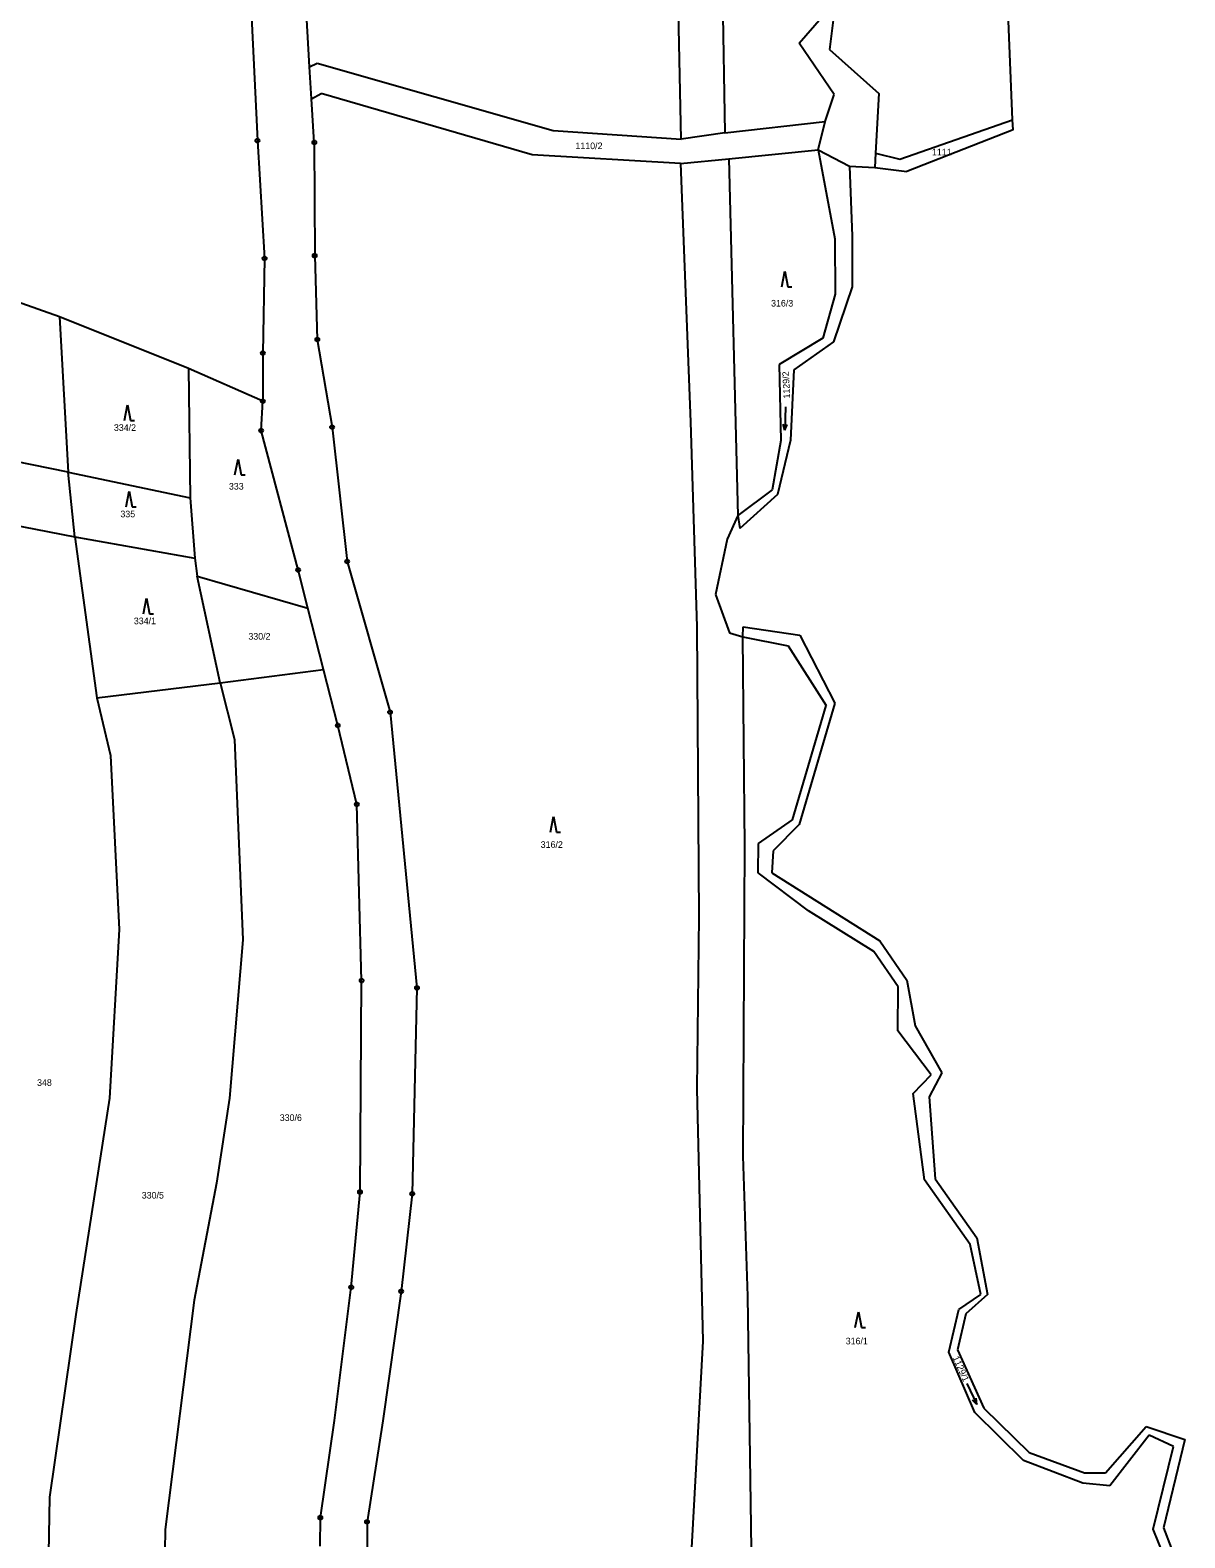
# Model space of a CAD drawing. Extents: x -794142 to -791199, y -1109267 to -1105626.
# Drawn here: x -792350.1 to -792053.1, y -1106886 to -1106498.2 of the extents above; entities that cross this region are included whole.
import ezdxf

# ---------------------------------------------------------------- set-up
doc = ezdxf.new("R2010")
doc.units = 0
for name, color, linetype in [('Vrstva 1', 7, 'Continuous'), ('Vrstva 14', 7, 'Continuous'), ('Vrstva 23', 7, 'Continuous'), ('Vrstva 28', 7, 'Continuous'), ('Vrstva 4', 7, 'Continuous')]:
    doc.layers.add(name, color=color, linetype=linetype)

msp = doc.modelspace()

# ---------------------------------------------------------------- linework, layer by layer
at = {"layer": 'Vrstva 1'}
for p, q in [((-792173.09, -1106426.36), (-792171.46, -1106524.59)), ((-792182.68, -1106526.22), (-792184.72, -1106430.3)), ((-792278.2, -1106507.65), (-792280.82, -1106464.66)), ((-792139.75, -1106464.02), (-792144.51, -1106503.18)), ((-792294.55, -1106465.43), (-792291.64, -1106526.62)), ((-792152.29, -1106501.53), (-792146.57, -1106494.99)), ((-792143.31, -1106514.79), (-792152.29, -1106501.53)), ((-792144.51, -1106503.18), (-792131.87, -1106514.52)), ((-792278.2, -1106507.65), (-792276.28, -1106506.69)), ((-792277.7, -1106515.86), (-792278.2, -1106507.65)), ((-792276.28, -1106506.69), (-792215.55, -1106524.04)), ((-792277.7, -1106515.86), (-792275.28, -1106514.53)), ((-792221.01, -1106530.25), (-792275.28, -1106514.53)), ((-792145.63, -1106521.72), (-792143.31, -1106514.79)), ((-792131.87, -1106514.52), (-792132.65, -1106529.9)), ((-792277.01, -1106527.1), (-792277.7, -1106515.86)), ((-792171.46, -1106524.59), (-792145.63, -1106521.72)), ((-792147.41, -1106529.04), (-792145.63, -1106521.72)), ((-792126.4, -1106531.43), (-792097.46, -1106521.3)), ((-792291.64, -1106526.62), (-792289.8, -1106556.92)), ((-792277.01, -1106527.1), (-792276.91, -1106556.22)), ((-792215.55, -1106524.04), (-792182.68, -1106526.22)), ((-792171.46, -1106524.59), (-792182.68, -1106526.22)), ((-792182.87, -1106532.49), (-792221.01, -1106530.25)), ((-792182.87, -1106532.49), (-792170.41, -1106531.28)), ((-792170.41, -1106531.28), (-792147.41, -1106529.04)), ((-792170.41, -1106531.28), (-792168.06, -1106623.03)), ((-792147.41, -1106529.04), (-792143.12, -1106551.85)), ((-792147.41, -1106529.04), (-792139.41, -1106533.21)), ((-792132.65, -1106529.9), (-792132.86, -1106533.57)), ((-792132.65, -1106529.9), (-792126.4, -1106531.43)), ((-792182.87, -1106532.49), (-792180.28, -1106598.96)), ((-792143.12, -1106551.85), (-792143.05, -1106566.11)), ((-792289.8, -1106556.92), (-792290.24, -1106581.27)), ((-792276.91, -1106556.22), (-792276.23, -1106577.77)), ((-792143.05, -1106566.11), (-792146.2, -1106577.44)), ((-792342.56, -1106571.94), (-792353.7, -1106568)), ((-792342.56, -1106571.94), (-792340.28, -1106611.92)), ((-792309.33, -1106585.21), (-792342.56, -1106571.94)), ((-792276.23, -1106577.77), (-792272.43, -1106600.33)), ((-792146.2, -1106577.44), (-792157.47, -1106584.23)), ((-792290.24, -1106581.27), (-792290.24, -1106593.67)), ((-792290.24, -1106593.67), (-792309.33, -1106585.21)), ((-792309.33, -1106585.21), (-792308.9, -1106618.5)), ((-792157.47, -1106584.23), (-792157, -1106603.73)), ((-792290.67, -1106601.2), (-792290.24, -1106593.67)), ((-792272.43, -1106600.33), (-792268.55, -1106634.86)), ((-792180.28, -1106598.96), (-792178.63, -1106651.72)), ((-792281.16, -1106637.04), (-792290.67, -1106601.2)), ((-792157, -1106603.73), (-792159.28, -1106616.41)), ((-792340.28, -1106611.92), (-792370.18, -1106605.87)), ((-792340.28, -1106611.92), (-792308.9, -1106618.5)), ((-792338.6, -1106628.51), (-792340.28, -1106611.92)), ((-792159.28, -1106616.41), (-792168.06, -1106623.03)), ((-792308.9, -1106618.5), (-792307.71, -1106633.98)), ((-792368.06, -1106622.79), (-792338.6, -1106628.51)), ((-792338.6, -1106628.51), (-792307.71, -1106633.98)), ((-792338.6, -1106628.51), (-792332.91, -1106669.92)), ((-792307.71, -1106633.98), (-792307.15, -1106638.68)), ((-792268.55, -1106634.86), (-792257.53, -1106673.63)), ((-792307.15, -1106638.68), (-792278.66, -1106646.86)), ((-792301.21, -1106666.11), (-792307.15, -1106638.68)), ((-792278.66, -1106646.86), (-792281.16, -1106637.04)), ((-792274.62, -1106662.68), (-792278.66, -1106646.86)), ((-792178.63, -1106651.72), (-792178.12, -1106726.25)), ((-792166.82, -1106654.29), (-792155.12, -1106656.54)), ((-792166.28, -1106708.06), (-792166.82, -1106654.29)), ((-792155.12, -1106656.54), (-792145.41, -1106671.91)), ((-792301.21, -1106666.11), (-792274.62, -1106662.68)), ((-792270.96, -1106677.04), (-792274.62, -1106662.68)), ((-792332.91, -1106669.92), (-792301.21, -1106666.11)), ((-792301.21, -1106666.11), (-792297.51, -1106680.66)), ((-792332.91, -1106669.92), (-792329.38, -1106684.74)), ((-792257.53, -1106673.63), (-792250.6, -1106744.55)), ((-792154.05, -1106701.34), (-792145.41, -1106671.91)), ((-792266.07, -1106697.34), (-792270.96, -1106677.04)), ((-792297.51, -1106680.66), (-792295.35, -1106732.22)), ((-792329.38, -1106684.74), (-792327.21, -1106729.54)), ((-792264.84, -1106742.65), (-792266.07, -1106697.34)), ((-792162.76, -1106707.37), (-792154.05, -1106701.34)), ((-792166.75, -1106787.84), (-792166.28, -1106708.06)), ((-792162.86, -1106714.98), (-792162.76, -1106707.37)), ((-792149.88, -1106724.72), (-792162.86, -1106714.98)), ((-792133.14, -1106735.14), (-792149.88, -1106724.72)), ((-792178.12, -1106726.25), (-792178.67, -1106770.51)), ((-792327.21, -1106729.54), (-792329.67, -1106772.89)), ((-792295.35, -1106732.22), (-792298.81, -1106772.87)), ((-792126.82, -1106744.25), (-792133.14, -1106735.14)), ((-792265.25, -1106797.04), (-792264.84, -1106742.65)), ((-792250.6, -1106744.55), (-792251.82, -1106797.49)), ((-792126.91, -1106755.57), (-792126.82, -1106744.25)), ((-792118.38, -1106766.88), (-792126.91, -1106755.57)), ((-792123.03, -1106771.66), (-792118.38, -1106766.88)), ((-792178.67, -1106770.51), (-792177.09, -1106835.36)), ((-792120.09, -1106793.89), (-792123.03, -1106771.66)), ((-792329.67, -1106772.89), (-792338.31, -1106828.51)), ((-792298.81, -1106772.87), (-792302.12, -1106794.72)), ((-792165.5, -1106823.84), (-792166.75, -1106787.84)), ((-792302.12, -1106794.72), (-792307.9, -1106824.89)), ((-792108.38, -1106810.53), (-792120.09, -1106793.89)), ((-792267.5, -1106821.53), (-792265.25, -1106797.04)), ((-792251.82, -1106797.49), (-792254.68, -1106822.59)), ((-792105.64, -1106823.36), (-792108.38, -1106810.53)), ((-792271.78, -1106855.81), (-792267.5, -1106821.53)), ((-792307.9, -1106824.89), (-792315.39, -1106883.85)), ((-792254.68, -1106822.59), (-792259.37, -1106855.86)), ((-792164.08, -1106923.34), (-792165.5, -1106823.84)), ((-792111.26, -1106827.26), (-792105.64, -1106823.36)), ((-792338.31, -1106828.51), (-792345.09, -1106875.54)), ((-792113.85, -1106838.2), (-792111.26, -1106827.26)), ((-792177.09, -1106835.36), (-792181.72, -1106918.62)), ((-792107.18, -1106853.7), (-792113.85, -1106838.2)), ((-792275.45, -1106880.79), (-792271.78, -1106855.81)), ((-792259.37, -1106855.86), (-792263.45, -1106881.86)), ((-792094.6, -1106866.1), (-792107.18, -1106853.7)), ((-792062.34, -1106859.6), (-792072.44, -1106872.59)), ((-792056.03, -1106862.48), (-792062.34, -1106859.6)), ((-792061.32, -1106883.76), (-792056.03, -1106862.48)), ((-792079.4, -1106871.94), (-792094.6, -1106866.1)), ((-792072.44, -1106872.59), (-792079.4, -1106871.94)), ((-792345.09, -1106875.54), (-792345.95, -1106926.06)), ((-792315.39, -1106883.85), (-792315.83, -1106918.43)), ((-792275.53, -1106888.11), (-792275.45, -1106880.79)), ((-792263.45, -1106881.86), (-792263.24, -1106898.39)), ((-792056.9, -1106894.59), (-792061.32, -1106883.76))]:
    msp.add_line(p, q, dxfattribs=at)
at = {"layer": 'Vrstva 23'}
for p, q in [((-792156.8, -1106564.2), (-792156, -1106560.2)), ((-792156, -1106560.2), (-792155.2, -1106564.2)), ((-792155.2, -1106564.2), (-792154.2, -1106564.2)), ((-792325.85, -1106598.58), (-792325.05, -1106594.58)), ((-792325.05, -1106594.58), (-792324.25, -1106598.58)), ((-792155.84, -1106595.1), (-792155.979, -1106601.099)), ((-792324.25, -1106598.58), (-792323.25, -1106598.58)), ((-792155.979, -1106601.099), (-792156.444, -1106599.588)), ((-792155.979, -1106601.099), (-792155.444, -1106599.611)), ((-792297.42, -1106612.57), (-792296.62, -1106608.57)), ((-792296.62, -1106608.57), (-792295.82, -1106612.57)), ((-792295.82, -1106612.57), (-792294.82, -1106612.57)), ((-792325.42, -1106620.8), (-792324.62, -1106616.8)), ((-792324.62, -1106616.8), (-792323.82, -1106620.8)), ((-792323.82, -1106620.8), (-792322.82, -1106620.8)), ((-792320.95, -1106648.3), (-792320.15, -1106644.3)), ((-792320.15, -1106644.3), (-792319.35, -1106648.3)), ((-792319.35, -1106648.3), (-792318.35, -1106648.3)), ((-792216.29, -1106704.47), (-792215.49, -1106700.47)), ((-792215.49, -1106700.47), (-792214.69, -1106704.47)), ((-792214.69, -1106704.47), (-792213.69, -1106704.47)), ((-792137.89, -1106831.86), (-792137.09, -1106827.86)), ((-792137.09, -1106827.86), (-792136.29, -1106831.86)), ((-792136.29, -1106831.86), (-792135.29, -1106831.86)), ((-792109.191, -1106846.252), (-792106.608, -1106851.667)), ((-792106.608, -1106851.667), (-792107.705, -1106850.529)), ((-792106.608, -1106851.667), (-792106.802, -1106850.098))]:
    msp.add_line(p, q, dxfattribs=at)
at = {"layer": 'Vrstva 28'}
for centre, radius in [((-792291.64, -1106526.62), 0.5), ((-792291.64, -1106526.62), 0.01), ((-792277.01, -1106527.1), 0.5), ((-792277.01, -1106527.1), 0.01), ((-792289.8, -1106556.92), 0.5), ((-792289.8, -1106556.92), 0.01), ((-792276.91, -1106556.22), 0.5), ((-792276.91, -1106556.22), 0.01), ((-792276.23, -1106577.77), 0.5), ((-792276.23, -1106577.77), 0.01), ((-792290.24, -1106581.27), 0.5), ((-792290.24, -1106581.27), 0.01), ((-792290.24, -1106593.67), 0.5), ((-792290.24, -1106593.67), 0.01), ((-792290.67, -1106601.2), 0.5), ((-792272.43, -1106600.33), 0.5), ((-792272.43, -1106600.33), 0.01), ((-792290.67, -1106601.2), 0.01), ((-792268.55, -1106634.86), 0.5), ((-792268.55, -1106634.86), 0.01), ((-792281.16, -1106637.04), 0.5), ((-792281.16, -1106637.04), 0.01), ((-792257.53, -1106673.63), 0.5), ((-792257.53, -1106673.63), 0.01), ((-792270.96, -1106677.04), 0.5), ((-792270.96, -1106677.04), 0.01), ((-792266.07, -1106697.34), 0.5), ((-792266.07, -1106697.34), 0.01), ((-792264.84, -1106742.65), 0.5), ((-792264.84, -1106742.65), 0.01), ((-792250.6, -1106744.55), 0.5), ((-792250.6, -1106744.55), 0.01), ((-792265.25, -1106797.04), 0.5), ((-792265.25, -1106797.04), 0.01), ((-792251.82, -1106797.49), 0.5), ((-792251.82, -1106797.49), 0.01), ((-792267.5, -1106821.53), 0.5), ((-792267.5, -1106821.53), 0.01), ((-792254.68, -1106822.59), 0.5), ((-792254.68, -1106822.59), 0.01), ((-792275.45, -1106880.79), 0.5), ((-792275.45, -1106880.79), 0.01), ((-792263.45, -1106881.86), 0.5), ((-792263.45, -1106881.86), 0.01)]:
    msp.add_circle(centre, radius, dxfattribs=at)
at = {"layer": 'Vrstva 4'}
for p, q in [((-792097.46, -1106521.3), (-792099.86, -1106461.47)), ((-792097.25, -1106523.84), (-792097.46, -1106521.3)), ((-792097.25, -1106523.84), (-792124.63, -1106534.61)), ((-792139.41, -1106533.21), (-792138.73, -1106551.22)), ((-792139.41, -1106533.21), (-792132.86, -1106533.57)), ((-792132.86, -1106533.57), (-792124.63, -1106534.61)), ((-792138.73, -1106551.22), (-792138.72, -1106564.22)), ((-792138.72, -1106564.22), (-792143.49, -1106578.36)), ((-792143.49, -1106578.36), (-792153.72, -1106585.55)), ((-792153.72, -1106585.55), (-792154.59, -1106603.71)), ((-792154.59, -1106603.71), (-792157.91, -1106617.66)), ((-792157.91, -1106617.66), (-792167.58, -1106626.39)), ((-792168.06, -1106623.03), (-792170.81, -1106629.15)), ((-792168.06, -1106623.03), (-792167.58, -1106626.39)), ((-792170.81, -1106629.15), (-792173.87, -1106643.33)), ((-792173.87, -1106643.33), (-792170.25, -1106653.26)), ((-792170.25, -1106653.26), (-792166.82, -1106654.29)), ((-792166.82, -1106654.29), (-792166.75, -1106651.68)), ((-792166.75, -1106651.68), (-792152.14, -1106653.79)), ((-792152.14, -1106653.79), (-792143.13, -1106671.28)), ((-792143.13, -1106671.28), (-792152.3, -1106702.52)), ((-792152.3, -1106702.52), (-792159.04, -1106709.26)), ((-792159.04, -1106709.26), (-792159.32, -1106714.98)), ((-792159.32, -1106714.98), (-792131.55, -1106732.44)), ((-792131.55, -1106732.44), (-792124.61, -1106742.54)), ((-792124.61, -1106742.54), (-792122.45, -1106754.26)), ((-792122.45, -1106754.26), (-792115.66, -1106766.39)), ((-792115.66, -1106766.39), (-792118.93, -1106772.58)), ((-792118.93, -1106772.58), (-792117.37, -1106793.62)), ((-792117.37, -1106793.62), (-792106.61, -1106808.82)), ((-792106.61, -1106808.82), (-792103.87, -1106823.37)), ((-792103.87, -1106823.37), (-792109.46, -1106828.38)), ((-792109.46, -1106828.38), (-792111.58, -1106837.65)), ((-792111.58, -1106837.65), (-792104.8, -1106852.66)), ((-792104.8, -1106852.66), (-792093.2, -1106864.06)), ((-792073.53, -1106869.22), (-792063.12, -1106857.35)), ((-792063.12, -1106857.35), (-792053.14, -1106860.72)), ((-792053.14, -1106860.72), (-792058.59, -1106883.4)), ((-792093.2, -1106864.06), (-792078.92, -1106869.27)), ((-792078.92, -1106869.27), (-792073.53, -1106869.22)), ((-792058.59, -1106883.4), (-792054.71, -1106893.69))]:
    msp.add_line(p, q, dxfattribs=at)

# ---------------------------------------------------------------- texts
at = {"layer": 'Vrstva 14'}
for s, p in [('1110/2', (-792209.849, -1106528.82)), ('1111', (-792118.169, -1106530.44)), ('316/3', (-792159.543, -1106569.3)), ('334/2', (-792328.536, -1106601.28)), ('333', (-792298.967, -1106616.38)), ('335', (-792326.873, -1106623.5)), ('334/1', (-792323.409, -1106651)), ('330/2', (-792293.959, -1106654.98)), ('316/2', (-792218.783, -1106708.52)), ('348', (-792348.302, -1106769.74)), ('330/6', (-792285.889, -1106778.76)), ('330/5', (-792321.376, -1106798.72)), ('316/1', (-792140.346, -1106836.21))]:
    msp.add_text(s, height=1.7, dxfattribs=at).set_placement(p)
for s, rotation, p in [('1129/2', 92.64042, (-792154.646, -1106592.912)), ('1129/1', 294.03963, (-792112.907, -1106839.656))]:
    msp.add_text(s, height=1.7, rotation=rotation, dxfattribs=at).set_placement(p)

doc.saveas('drawing.dxf')
